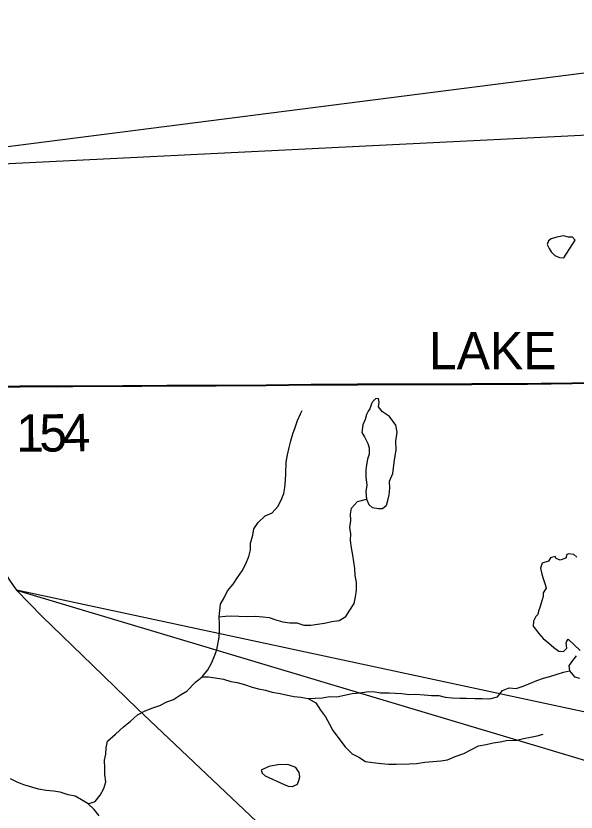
# Model space of a CAD drawing. Extents: x 0 to 34, y 0 to 22.
# Drawn here: x 5.262 to 6.114, y 16.855 to 18.065 of the extents above; entities that cross this region are included whole.
import ezdxf

# ---------------------------------------------------------------- set-up
doc = ezdxf.new("R2010")
doc.units = 0
for name, color, linetype in [('GM_X_Corporation', 7, 'Continuous'), ('GM_X_County_Road', 7, 'Continuous'), ('GM_X_County_Road_Text', 7, 'Continuous'), ('GM_X_Minor_Lake', 7, 'Continuous'), ('GM_X_Minor_River', 7, 'Continuous'), ('GM_X_State_Location', 7, 'Continuous'), ('SH_Data', 7, 'Continuous'), ('SH_Text', 7, 'Continuous')]:
    doc.layers.add(name, color=color, linetype=linetype)

msp = doc.modelspace()

# ---------------------------------------------------------------- linework, layer by layer
at = {"layer": 'GM_X_Corporation'}
for points in [[(6.1478, 17.5073), (6.108, 17.507), (6.0757, 17.5065), (6.0608, 17.5062), (6.0397, 17.506), (6.0211, 17.506), (5.987, 17.5059), (5.9554, 17.5056), (5.9374, 17.5054), (5.9325, 17.5054), (5.9306, 17.5053), (5.925, 17.5052), (5.9089, 17.5052), (5.8723, 17.5053), (5.8555, 17.5053), (5.8319, 17.5053), (5.8127, 17.5052), (5.7818, 17.5051), (5.7539, 17.5049), (5.7384, 17.5049), (5.711, 17.5048), (5.6427, 17.5039), (5.5663, 17.5035), (5.4917, 17.5032), (5.4533, 17.5029), (5.4458, 17.5028), (5.4248, 17.5029), (5.3483, 17.5021), (5.3247, 17.5021), (5.2974, 17.5023), (5.2682, 17.5021), (5.2477, 17.5019)], [(5.2477, 17.5019), (5.2682, 17.5021), (5.2974, 17.5023), (5.3247, 17.5021), (5.3483, 17.5021), (5.4248, 17.5029), (5.4458, 17.5028), (5.4533, 17.5029), (5.4917, 17.5032), (5.5663, 17.5035), (5.6427, 17.5039), (5.711, 17.5048), (5.7384, 17.5049), (5.7539, 17.5049), (5.7818, 17.5051), (5.8127, 17.5052), (5.8319, 17.5053), (5.8555, 17.5053), (5.8723, 17.5053), (5.9089, 17.5052), (5.925, 17.5052), (5.9306, 17.5053), (5.9325, 17.5054), (5.9374, 17.5054), (5.9554, 17.5056), (5.987, 17.5059), (6.0211, 17.506), (6.0397, 17.506), (6.0608, 17.5062), (6.0757, 17.5065), (6.108, 17.507), (6.1478, 17.5073)]]:
    msp.add_lwpolyline(points, dxfattribs=at)
at = {"layer": 'GM_X_County_Road'}
msp.add_lwpolyline([(5.2479, 17.5014), (5.2684, 17.5015), (5.2976, 17.5017), (5.3249, 17.5015), (5.3485, 17.5016), (5.425, 17.5023), (5.4461, 17.5023), (5.4535, 17.5023), (5.4919, 17.5027), (5.5665, 17.5029), (5.6429, 17.5033), (5.7112, 17.5043), (5.7386, 17.5043), (5.7541, 17.5044), (5.782, 17.5045), (5.8129, 17.5046), (5.8321, 17.5047), (5.8557, 17.5048), (5.8725, 17.5047), (5.9091, 17.5047), (5.9253, 17.5046), (5.9308, 17.5048), (5.9327, 17.5048), (5.9376, 17.5048), (5.9556, 17.505), (5.9872, 17.5053), (6.0213, 17.5055), (6.0399, 17.5055), (6.061, 17.5056), (6.0759, 17.5059), (6.1082, 17.5065), (6.148, 17.5068)], dxfattribs=at)
at = {"layer": 'GM_X_Minor_Lake'}
for p, q in [((6.0955, 17.6972), (6.1127, 17.7242)), ((5.831, 17.3474), (5.8305, 17.3576)), ((5.6414, 16.9099), (5.6703, 16.8964))]:
    msp.add_line(p, q, dxfattribs=at)
for points in [[(6.1127, 17.7242), (6.1085, 17.7287), (6.1024, 17.7291), (6.0948, 17.7309), (6.0846, 17.7289), (6.0759, 17.7262), (6.0718, 17.7235), (6.0699, 17.7178), (6.073, 17.7118), (6.0761, 17.7065), (6.0818, 17.7009), (6.089, 17.6979), (6.0955, 17.6972)], [(5.8305, 17.3576), (5.8354, 17.3694), (5.8368, 17.3823), (5.8378, 17.3899), (5.8404, 17.4055), (5.8399, 17.4187), (5.8417, 17.4324), (5.8401, 17.443), (5.8301, 17.4562), (5.8195, 17.4633), (5.8137, 17.4709), (5.8144, 17.4781), (5.8133, 17.4834), (5.8091, 17.483), (5.8046, 17.4784), (5.8027, 17.4753), (5.8001, 17.4677), (5.7979, 17.4643), (5.7953, 17.459), (5.7935, 17.4514), (5.7897, 17.4434), (5.7883, 17.4316), (5.7922, 17.4252), (5.7972, 17.415), (5.7991, 17.4086), (5.7995, 17.3991), (5.7966, 17.3911), (5.7951, 17.3828), (5.7944, 17.3744), (5.7945, 17.3642), (5.7958, 17.3517), (5.7943, 17.3422), (5.7952, 17.3304), (5.799, 17.3225), (5.804, 17.318), (5.8134, 17.3162), (5.8195, 17.3162), (5.8255, 17.3212), (5.8277, 17.3284), (5.8296, 17.3371), (5.831, 17.3474)], [(6.1149, 17.2422), (6.1107, 17.2464), (6.1028, 17.2475), (6.1001, 17.2463), (6.0986, 17.2406), (6.09, 17.2375), (6.0839, 17.2401), (6.0824, 17.2431), (6.0752, 17.2412), (6.0718, 17.2362), (6.0624, 17.2331), (6.0598, 17.2255), (6.0617, 17.2164), (6.0641, 17.21), (6.0672, 17.2005), (6.0683, 17.1952), (6.0639, 17.188), (6.0639, 17.1823), (6.061, 17.1724), (6.0591, 17.1656), (6.0569, 17.1599), (6.0558, 17.1553), (6.0528, 17.1519), (6.0491, 17.145), (6.0487, 17.1374), (6.0572, 17.1261), (6.0637, 17.1186), (6.072, 17.1122), (6.08, 17.1047), (6.088, 17.0991), (6.0948, 17.0987), (6.0997, 17.1041), (6.0989, 17.1117), (6.1, 17.1143), (6.1019, 17.1174), (6.1202, 17.1005)], [(6.1142, 17.0921), (6.1071, 17.0833), (6.103, 17.0772), (6.1038, 17.0692), (6.1118, 17.0602), (6.119, 17.058)], [(5.6703, 16.8964), (5.6764, 16.8942), (5.6828, 16.8935), (5.6903, 16.8973), (5.6922, 16.9027), (5.6937, 16.9084), (5.6928, 16.9148), (5.6879, 16.9223), (5.6757, 16.9268), (5.6602, 16.9263), (5.647, 16.9239), (5.6353, 16.9185), (5.6365, 16.9136), (5.6414, 16.9099)]]:
    msp.add_lwpolyline(points, dxfattribs=at)
at = {"layer": 'GM_X_Minor_River'}
for points in [[(5.3719, 16.8672), (5.3829, 16.8707), (5.3903, 16.8802), (5.3959, 16.8905), (5.3989, 16.9004), (5.3973, 16.9118), (5.3976, 16.9212), (5.3971, 16.9334), (5.3989, 16.9429), (5.3992, 16.9524), (5.4014, 16.9622), (5.4138, 16.9729), (5.4259, 16.9844), (5.436, 16.9921), (5.4469, 17.0024), (5.4575, 17.0082), (5.4688, 17.0128), (5.4809, 17.0167), (5.4914, 17.0225), (5.502, 17.0259), (5.5125, 17.0329), (5.5223, 17.0386), (5.5351, 17.052), (5.5452, 17.0604), (5.5539, 17.0707), (5.5598, 17.081), (5.5635, 17.0909), (5.5676, 17.1015), (5.5712, 17.1205), (5.5719, 17.1308), (5.5715, 17.1406), (5.571, 17.1516), (5.5721, 17.1611), (5.5731, 17.171), (5.5787, 17.1805), (5.5839, 17.1908), (5.5926, 17.2011), (5.5993, 17.2114), (5.606, 17.2213), (5.612, 17.2323), (5.6161, 17.2434), (5.619, 17.2532), (5.6189, 17.2635), (5.6223, 17.2756), (5.6241, 17.2851), (5.6304, 17.295), (5.641, 17.305), (5.6519, 17.3096), (5.6605, 17.3195), (5.6657, 17.3291), (5.6698, 17.3389), (5.6713, 17.3484), (5.6723, 17.3591), (5.6726, 17.3693), (5.6732, 17.3868), (5.675, 17.3981), (5.6776, 17.4088), (5.6802, 17.419), (5.6831, 17.4297), (5.6868, 17.4396), (5.6905, 17.4502), (5.695, 17.4601), (5.6976, 17.4651)], [(5.571, 17.1516), (5.5808, 17.1524), (5.5907, 17.1529), (5.6013, 17.1526), (5.6149, 17.152), (5.6266, 17.1524), (5.6376, 17.1514), (5.6475, 17.1503), (5.6573, 17.147), (5.6683, 17.144), (5.6789, 17.1426), (5.6895, 17.1423), (5.7002, 17.139), (5.7108, 17.139), (5.721, 17.1403), (5.7316, 17.1418), (5.7425, 17.1446), (5.7538, 17.1458), (5.7636, 17.152), (5.77, 17.1615), (5.7764, 17.1718), (5.7785, 17.182), (5.78, 17.1923), (5.7799, 17.2036), (5.7779, 17.2146), (5.7774, 17.2252), (5.7759, 17.2351), (5.7743, 17.2453), (5.7727, 17.2563), (5.7707, 17.2677), (5.7714, 17.2775), (5.7701, 17.2874), (5.7716, 17.298), (5.7711, 17.3075), (5.7726, 17.317), (5.7816, 17.3269), (5.7952, 17.3304)], [(5.5452, 17.0604), (5.5551, 17.0601), (5.5653, 17.059), (5.5778, 17.0565), (5.5888, 17.0532), (5.5987, 17.0517), (5.6097, 17.0488), (5.6214, 17.0447), (5.6309, 17.0421), (5.6415, 17.0399), (5.6518, 17.037), (5.6639, 17.0348), (5.6753, 17.0326), (5.6851, 17.0304), (5.6953, 17.0293), (5.7067, 17.0275), (5.7173, 17.0276), (5.7279, 17.0281), (5.7389, 17.0304), (5.7502, 17.0297), (5.7619, 17.0325), (5.7736, 17.0349), (5.7854, 17.0357), (5.7952, 17.0373), (5.8058, 17.0378), (5.8168, 17.0359), (5.8297, 17.036), (5.849, 17.0347), (5.8603, 17.0336), (5.8705, 17.0337), (5.883, 17.033), (5.894, 17.032), (5.9054, 17.0317), (5.9149, 17.0295), (5.9258, 17.0281), (5.9372, 17.0278), (5.9474, 17.0278), (5.9603, 17.0272), (5.9713, 17.0273), (5.9826, 17.027), (5.9943, 17.0297), (6.0022, 17.0393), (6.0124, 17.0435), (6.023, 17.0425), (6.0336, 17.0459), (6.0445, 17.0506), (6.0543, 17.0548), (6.0645, 17.0583), (6.0743, 17.061), (6.0853, 17.0642), (6.0951, 17.0673), (6.1038, 17.0692)], [(5.7067, 17.0275), (5.7181, 17.0208), (5.7254, 17.0098), (5.7327, 16.9993), (5.7388, 16.9883), (5.7442, 16.9785), (5.7626, 16.9536), (5.7736, 16.9431), (5.7835, 16.9379), (5.7938, 16.9315), (5.8048, 16.9301), (5.818, 16.9283), (5.8286, 16.9276), (5.8403, 16.9277), (5.8604, 16.9278), (5.8714, 16.9287), (5.8842, 16.9303), (5.8963, 16.9315), (5.9081, 16.9327), (5.9186, 16.9343), (5.9303, 16.939), (5.9432, 16.9436), (5.9658, 16.9552), (5.9771, 16.9575), (5.9881, 16.9599), (5.9987, 16.9615), (6.01, 16.9639), (6.0217, 16.9632), (6.0338, 16.9663), (6.0448, 16.9683), (6.0546, 16.9703), (6.0637, 16.973)], [(5.3719, 16.8672), (5.362, 16.8732), (5.3525, 16.8788), (5.3415, 16.881), (5.3294, 16.8847), (5.3191, 16.8865), (5.3082, 16.8876), (5.2964, 16.8894), (5.2744, 16.896), (5.2642, 16.9001), (5.2539, 16.905)], [(5.3887, 16.8488), (5.3814, 16.8586), (5.3719, 16.8672)]]:
    msp.add_lwpolyline(points, dxfattribs=at)
at = {"layer": 'SH_Data'}
msp.add_lwpolyline([(4.9237, 17.8249), (5.2441, 17.2203), (5.2514, 17.2089), (5.259, 17.1975), (5.2632, 17.1919)], dxfattribs=at)
at = {"layer": 'SH_Text'}
for points in [[(9.3865, 18.3957), (4.9237, 17.8249), (9.3865, 18.0457)], [(9.3865, 16.3077), (5.2632, 17.1919), (9.3865, 15.9577)]]:
    msp.add_lwpolyline(points, close=True, dxfattribs=at)
msp.add_lwpolyline([(5.2632, 17.1919), (5.3023, 17.152), (5.3786, 17.078), (5.4473, 17.0114), (5.6471, 16.8219), (5.8274, 16.6565)], dxfattribs=at)

# ---------------------------------------------------------------- texts
at = {"layer": 'GM_X_County_Road_Text'}
for s, height, rotation, p in [('LAKE', 0.05682, 0, (5.8901, 17.528)), ('1', 0.0568, 0.0545, (5.2626, 17.4028)), ('5', 0.0568, 0.2253, (5.2978, 17.4028)), ('4', 0.0568, 0.9903, (5.3336, 17.4029))]:
    msp.add_text(s, height=height, rotation=rotation, dxfattribs=at).set_placement(p)
at = {"layer": 'GM_X_State_Location'}
for s in ['s', 'r']:
    msp.add_text(s, height=0.000189, dxfattribs=at).set_placement((5.3919, 17.043))
msp.add_text('14', height=0.000189, rotation=0, dxfattribs=at).set_placement((5.3442, 17.0293))

doc.saveas('drawing.dxf')
